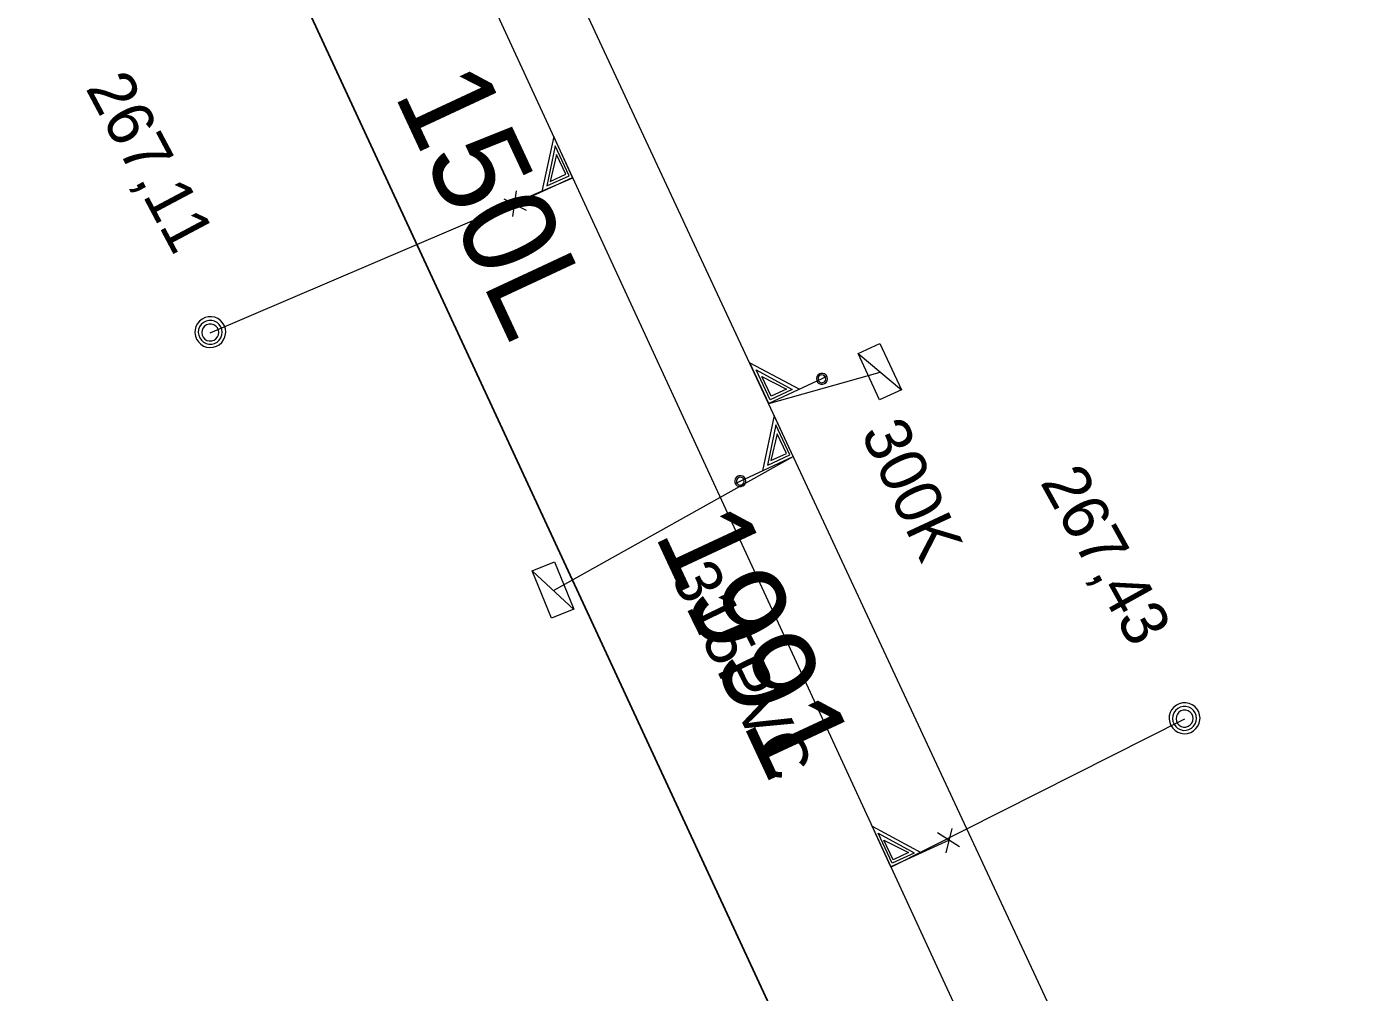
# Model space of a CAD drawing. Extents: x -732074 to -731966, y -1048695 to -1047982.
# Drawn here: x -732027.66 to -732004.91, y -1048532.64 to -1048516.11 of the extents above; entities that cross this region are included whole.
import ezdxf

# ---------------------------------------------------------------- set-up
doc = ezdxf.new("R2010")
doc.units = 0
doc.header["$LTSCALE"] = 0.32
doc.layers.add('1', color=7, linetype='Continuous')
for name, color, linetype, lineweight in [('18', 7, 'Continuous', 13), ('20', 7, 'Continuous', 13), ('49', 7, 'Continuous', 13), ('8', 7, 'Continuous', 13)]:
    doc.layers.add(name, color=color, linetype=linetype, lineweight=lineweight)

msp = doc.modelspace()

# ---------------------------------------------------------------- linework, layer by layer
at = {"layer": '18'}
for p, q in [((-732019.5, -1048519.055), (-732019.115, -1048519.247)), ((-732019.346, -1048519.357), (-732019.28, -1048518.918)), ((-732013.435, -1048521.706), (-732012.695, -1048522.327)), ((-732019.009, -1048525.429), (-732018.3, -1048526.084)), ((-732011.699, -1048530.146), (-732012.076, -1048529.911)), ((-732011.83, -1048529.834), (-732011.933, -1048530.25))]:
    msp.add_line(p, q, dxfattribs=at)
for points in [[(-732019.315, -1048519.147), (-732018.32, -1048518.688), (-732018.643, -1048517.988), (-732018.845, -1048518.93)], [(-732018.759, -1048518.834), (-732018.382, -1048518.66), (-732018.618, -1048518.147), (-732018.76, -1048518.835)], [(-732018.703, -1048518.757), (-732018.439, -1048518.635), (-732018.594, -1048518.298), (-732018.702, -1048518.758)], [(-732013.969, -1048522.097), (-732014.961, -1048522.56), (-732015.286, -1048521.862), (-732014.437, -1048522.315)], [(-732014.565, -1048522.32), (-732014.942, -1048522.496), (-732015.181, -1048521.983), (-732014.564, -1048522.319)], [(-732014.661, -1048522.313), (-732014.926, -1048522.436), (-732015.083, -1048522.099), (-732014.661, -1048522.314)], [(-732015.538, -1048523.929), (-732014.545, -1048523.466), (-732014.871, -1048522.767), (-732015.069, -1048523.71)], [(-732014.983, -1048523.614), (-732014.606, -1048523.438), (-732014.845, -1048522.925), (-732014.985, -1048523.615)], [(-732014.927, -1048523.536), (-732014.663, -1048523.413), (-732014.82, -1048523.077), (-732014.927, -1048523.537)], [(-732011.88, -1048530.033), (-732012.874, -1048530.492), (-732013.196, -1048529.792), (-732012.349, -1048530.249)], [(-732012.478, -1048530.254), (-732012.855, -1048530.428), (-732013.092, -1048529.914), (-732012.476, -1048530.253)], [(-732012.573, -1048530.246), (-732012.838, -1048530.368), (-732012.994, -1048530.031), (-732012.573, -1048530.247)]]:
    msp.add_lwpolyline(points, dxfattribs=at)
for points in [[(-732024.256, -1048521.337), (-732024.262, -1048521.281), (-732024.279, -1048521.228), (-732024.308, -1048521.179), (-732024.346, -1048521.138), (-732024.392, -1048521.106), (-732024.444, -1048521.084), (-732024.499, -1048521.073), (-732024.555, -1048521.075), (-732024.61, -1048521.088), (-732024.661, -1048521.113), (-732024.705, -1048521.148), (-732024.741, -1048521.191), (-732024.766, -1048521.241), (-732024.781, -1048521.296), (-732024.784, -1048521.352), (-732024.775, -1048521.407), (-732024.754, -1048521.46), (-732024.723, -1048521.506), (-732024.683, -1048521.545), (-732024.635, -1048521.575), (-732024.582, -1048521.594), (-732024.526, -1048521.601), (-732024.47, -1048521.597), (-732024.416, -1048521.58), (-732024.367, -1048521.553), (-732024.325, -1048521.515), (-732024.292, -1048521.47), (-732024.269, -1048521.419), (-732024.257, -1048521.364)], [(-732024.315, -1048521.34), (-732024.321, -1048521.291), (-732024.339, -1048521.245), (-732024.367, -1048521.204), (-732024.404, -1048521.171), (-732024.448, -1048521.149), (-732024.496, -1048521.137), (-732024.545, -1048521.137), (-732024.593, -1048521.149), (-732024.637, -1048521.172), (-732024.674, -1048521.205), (-732024.702, -1048521.246), (-732024.719, -1048521.293), (-732024.725, -1048521.342), (-732024.718, -1048521.391), (-732024.7, -1048521.437), (-732024.672, -1048521.477), (-732024.635, -1048521.51), (-732024.591, -1048521.532), (-732024.542, -1048521.544), (-732024.493, -1048521.543), (-732024.445, -1048521.531), (-732024.402, -1048521.507), (-732024.365, -1048521.474), (-732024.337, -1048521.433), (-732024.321, -1048521.386)], [(-732024.374, -1048521.344), (-732024.38, -1048521.302), (-732024.397, -1048521.264), (-732024.425, -1048521.233), (-732024.46, -1048521.21), (-732024.5, -1048521.199), (-732024.542, -1048521.199), (-732024.582, -1048521.211), (-732024.617, -1048521.234), (-732024.644, -1048521.266), (-732024.661, -1048521.304), (-732024.666, -1048521.345), (-732024.66, -1048521.387), (-732024.642, -1048521.424), (-732024.614, -1048521.456), (-732024.578, -1048521.478), (-732024.538, -1048521.489), (-732024.496, -1048521.488), (-732024.456, -1048521.475), (-732024.422, -1048521.452), (-732024.395, -1048521.419), (-732024.379, -1048521.381)], [(-732013.062, -1048521.53), (-732012.696, -1048522.324), (-732013.071, -1048522.496), (-732013.436, -1048521.703)], [(-732014.093, -1048522.051), (-732014.121, -1048522.071), (-732014.14, -1048522.098), (-732014.148, -1048522.131), (-732014.144, -1048522.164), (-732014.129, -1048522.193), (-732014.104, -1048522.216), (-732014.072, -1048522.229), (-732014.039, -1048522.23), (-732014.008, -1048522.219), (-732013.982, -1048522.198), (-732013.965, -1048522.169), (-732013.959, -1048522.135), (-732013.966, -1048522.103), (-732013.983, -1048522.074), (-732014.009, -1048522.053), (-732014.041, -1048522.043), (-732014.075, -1048522.045)], [(-732014.083, -1048522.076), (-732014.106, -1048522.093), (-732014.12, -1048522.118), (-732014.121, -1048522.146), (-732014.112, -1048522.172), (-732014.092, -1048522.193), (-732014.066, -1048522.203), (-732014.038, -1048522.202), (-732014.013, -1048522.189), (-732013.995, -1048522.168), (-732013.988, -1048522.14), (-732013.992, -1048522.112), (-732014.008, -1048522.089), (-732014.032, -1048522.074), (-732014.06, -1048522.07)], [(-732015.493, -1048523.803), (-732015.52, -1048523.823), (-732015.539, -1048523.85), (-732015.547, -1048523.883), (-732015.543, -1048523.916), (-732015.528, -1048523.945), (-732015.503, -1048523.968), (-732015.472, -1048523.981), (-732015.438, -1048523.982), (-732015.406, -1048523.971), (-732015.38, -1048523.949), (-732015.364, -1048523.921), (-732015.358, -1048523.888), (-732015.365, -1048523.855), (-732015.381, -1048523.826), (-732015.408, -1048523.805), (-732015.44, -1048523.795), (-732015.474, -1048523.796)], [(-732015.479, -1048523.827), (-732015.502, -1048523.844), (-732015.516, -1048523.869), (-732015.518, -1048523.897), (-732015.508, -1048523.924), (-732015.489, -1048523.944), (-732015.463, -1048523.955), (-732015.435, -1048523.954), (-732015.409, -1048523.941), (-732015.392, -1048523.918), (-732015.384, -1048523.892), (-732015.389, -1048523.863), (-732015.404, -1048523.84), (-732015.428, -1048523.825), (-732015.457, -1048523.821)], [(-732018.629, -1048525.27), (-732018.301, -1048526.081), (-732018.683, -1048526.235), (-732019.011, -1048525.425)], [(-732007.586, -1048527.947), (-732007.592, -1048527.891), (-732007.608, -1048527.838), (-732007.637, -1048527.789), (-732007.676, -1048527.748), (-732007.722, -1048527.716), (-732007.774, -1048527.694), (-732007.829, -1048527.683), (-732007.885, -1048527.685), (-732007.94, -1048527.698), (-732007.99, -1048527.723), (-732008.035, -1048527.758), (-732008.071, -1048527.801), (-732008.096, -1048527.851), (-732008.111, -1048527.906), (-732008.114, -1048527.962), (-732008.105, -1048528.017), (-732008.084, -1048528.07), (-732008.053, -1048528.116), (-732008.012, -1048528.155), (-732007.965, -1048528.185), (-732007.912, -1048528.204), (-732007.856, -1048528.211), (-732007.799, -1048528.207), (-732007.745, -1048528.19), (-732007.696, -1048528.163), (-732007.655, -1048528.125), (-732007.622, -1048528.08), (-732007.598, -1048528.029), (-732007.587, -1048527.974)], [(-732007.645, -1048527.95), (-732007.651, -1048527.901), (-732007.669, -1048527.855), (-732007.696, -1048527.814), (-732007.733, -1048527.781), (-732007.777, -1048527.759), (-732007.826, -1048527.747), (-732007.875, -1048527.747), (-732007.923, -1048527.759), (-732007.967, -1048527.782), (-732008.004, -1048527.815), (-732008.032, -1048527.856), (-732008.049, -1048527.903), (-732008.054, -1048527.952), (-732008.048, -1048528.001), (-732008.03, -1048528.047), (-732008.002, -1048528.087), (-732007.965, -1048528.12), (-732007.921, -1048528.142), (-732007.872, -1048528.154), (-732007.823, -1048528.153), (-732007.775, -1048528.141), (-732007.732, -1048528.117), (-732007.695, -1048528.084), (-732007.667, -1048528.043), (-732007.651, -1048527.996)], [(-732007.704, -1048527.954), (-732007.71, -1048527.912), (-732007.727, -1048527.874), (-732007.755, -1048527.843), (-732007.789, -1048527.82), (-732007.83, -1048527.809), (-732007.872, -1048527.809), (-732007.912, -1048527.821), (-732007.946, -1048527.844), (-732007.973, -1048527.876), (-732007.99, -1048527.914), (-732007.995, -1048527.955), (-732007.99, -1048527.997), (-732007.972, -1048528.034), (-732007.944, -1048528.066), (-732007.907, -1048528.088), (-732007.868, -1048528.099), (-732007.826, -1048528.098), (-732007.786, -1048528.085), (-732007.752, -1048528.062), (-732007.725, -1048528.029), (-732007.709, -1048527.991)]]:
    msp.add_lwpolyline(points, close=True, dxfattribs=at)
at = {"layer": '20'}
msp.add_line((-732004.91, -1048544.13), (-732020.46, -1048510.78), dxfattribs=at)
msp.add_line((-732004.91, -1048544.13), (-732020.46, -1048510.78), dxfattribs=at)
msp.add_lwpolyline([(-732006.969, -1048543.29), (-732012.87, -1048530.498), (-732018.316, -1048518.694), (-732022.17, -1048510.34)], dxfattribs=at)
msp.add_lwpolyline([(-732006.969, -1048543.29), (-732012.87, -1048530.498), (-732018.316, -1048518.694), (-732022.17, -1048510.34)], dxfattribs=at)
at = {"layer": '49'}
for p, q in [((-732024.52, -1048521.35), (-732018.316, -1048518.694)), ((-732024.52, -1048521.35), (-732018.316, -1048518.694)), ((-732014.966, -1048522.561), (-732013.059, -1048522.02)), ((-732014.966, -1048522.561), (-732013.059, -1048522.02)), ((-732018.649, -1048525.76), (-732014.544, -1048523.467)), ((-732018.649, -1048525.76), (-732014.544, -1048523.467)), ((-732007.85, -1048527.96), (-732012.87, -1048530.498)), ((-732007.85, -1048527.96), (-732012.87, -1048530.498))]:
    msp.add_line(p, q, dxfattribs=at)
at = {"layer": '8', "lineweight": 25}
msp.add_lwpolyline([(-732043.199, -1048472.29), (-732042.854, -1048473.025), (-732034.093, -1048491.956), (-732023.079, -1048515.311), (-732013.932, -1048535.062), (-732012.27, -1048538.65), (-732009.129, -1048546.26)], dxfattribs=at)

# ---------------------------------------------------------------- texts
at = {"layer": '1'}
for s, height, rotation, p in [('267,11', 0.8, 298, (-732026.663, -1048517.158)), ('150L', 1.6, 295, (-732021.384, -1048517.257)), ('300K', 0.8, 295, (-732013.398, -1048523.061)), ('267,43', 0.8, 299, (-732010.331, -1048523.906)), ('1991', 1.6, 295, (-732016.932, -1048524.789)), ('315PVC', 0.8, 296, (-732016.65, -1048525.505))]:
    msp.add_text(s, height=height, rotation=rotation, dxfattribs=at).set_placement(p)

doc.saveas('drawing.dxf')
